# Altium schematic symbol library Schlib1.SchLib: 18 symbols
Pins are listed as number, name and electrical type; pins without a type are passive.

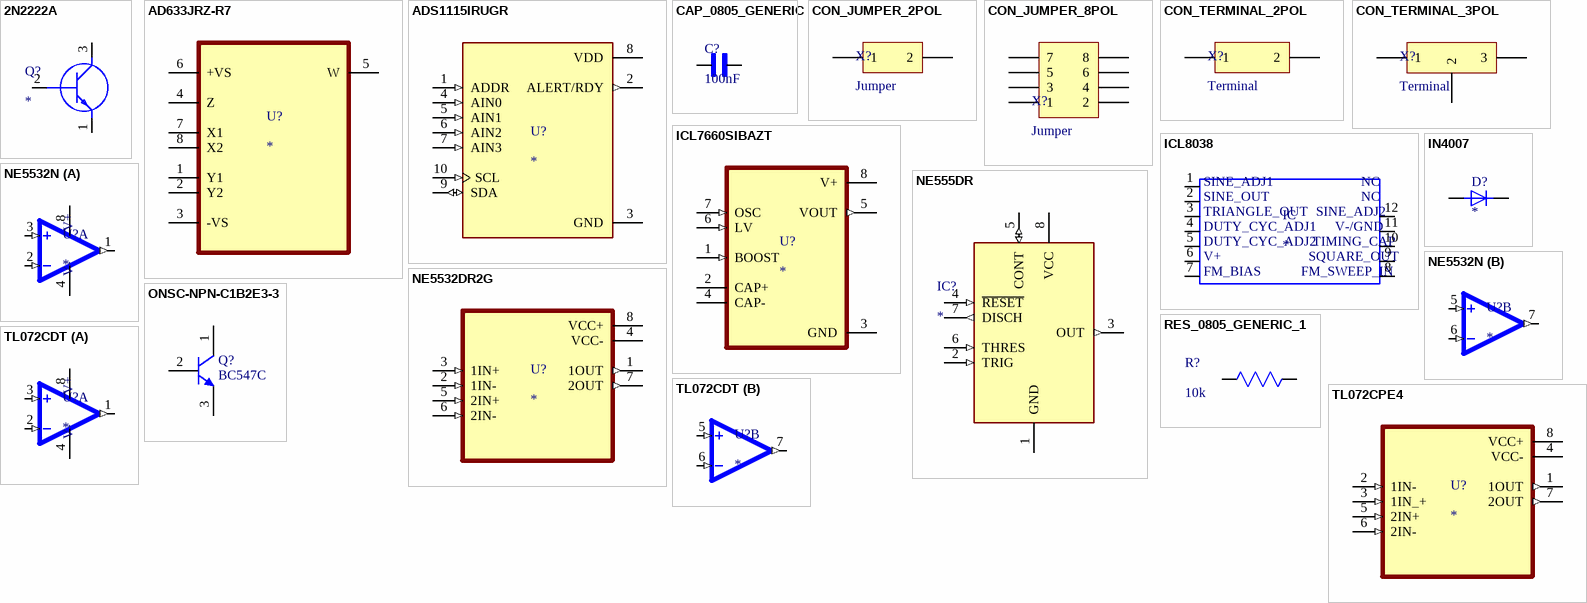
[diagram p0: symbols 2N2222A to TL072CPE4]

## 2N2222A
designator Q?
Transistor BJT NPN; Manufacturer_Name: Diotec; Manufacturer_Part_Number: 2N2222A
footprint 2N2222A
pins: 1 E, 2 B, 3 C

## AD633JRZ-R7
designator U?
Analog Multiplier 4-Quadrant 8-SOIC; MF: Analog Devices; MP: AD633AR
footprint SOIC127P600X175-8N
pins: 1 Y1, 2 Y2, 3 -VS (power), 4 Z, 5 W, 6 +VS (power), 7 X1, 8 X2

## ADS1115IRUGR
designator U?
16-bit, 860-SPS, 4-channel, delta-sigma ADC with PGA, oscillator, VREF, comparator and I2C; MF: Texas Instruments; MP: ADS1115IRUGR
footprint IC_ADS1115IRUGR
pins: 1 ADDR (in), 2 ALERT/RDY (out), 3 GND (power), 4 AIN0 (in), 5 AIN1 (in), 6 AIN2 (in), 7 AIN3 (in), 8 VDD (power), 9 SDA (io), 10 SCL (in)

## CAP_0805_GENERIC
designator C?, comment 100nF
0.1 ÂµF Â±10% 50V Ceramic Capacitor X7R 0805 (2012 Metric); MF: Samsung Electro-Mechanics; MP: CL21B104KBCNNNC
footprint CAPC2012X95N
pins: 1, 2

## CON_JUMPER_2POL
designator X?, comment Jumper
Manufacturer_Name: Yageo; Manufacturer_Part_Number: RC0805FR-0710KL; Value: 10k
footprint CON_JUMPER_2POL (Jumper)
pins: 1, 2

## CON_JUMPER_8POL
designator X?, comment Jumper
Manufacturer_Name: Yageo; Manufacturer_Part_Number: RC0805FR-0710KL; Value: 10k
footprint CON_JUMPER_8POL (Jumper)
pins: 1, 2, 3, 4, 5, 6, 7, 8

## CON_TERMINAL_2POL
designator X?, comment Terminal
Terminal Screw; Manufacturer_Name: Yageo; Manufacturer_Part_Number: RC0805FR-0710KL; Value: 10k
footprint CON_TERMINAL_2POL (Terminal Screw)
pins: 1, 2

## CON_TERMINAL_3POL
designator X?, comment Terminal
Terminal block; Manufacturer_Name: Yageo; Manufacturer_Part_Number: RC0805FR-0710KL; Value: 10k
footprint CON_TERMINAL_3POL (Terminal Screw)
pins: 1, 2, 3

## ICL7660SIBAZT
designator U?
Charge Pump Switching Regulator IC Positive or Negative Fixed -Vin, 2Vin 1 Output 45mA 8-SOIC (0.154, 3.90mm Width); MF: Renesas Electronics America Inc; MP: ICL7660SIBAZT
footprint SOIC127P600X175-8N
pins: 1 BOOST (in), 2 CAP+, 3 GND (power), 4 CAP-, 5 VOUT (out), 6 LV (in), 7 OSC (in), 8 V+ (power)

## ICL8038
designator IC
IC OSCILL GEN/VOLT CONTROL 14DIP; MF: Renesas Electronics; MP: ICL8038
footprint ICL8038
pins: 1, 2, 3, 4, 5, 6, 7, 8, 9, 10, 11, 12

## IN4007
designator D?
Diode Standard 1000 V 1A Through Hole DO-204AL (DO-41); MF: Vishay Semiconductor; MP: IN4007
footprint DIOAD1070W78L470D235P
pins: A, C

## NE555DR
designator IC?
Integrated Circuit; Manufacturer_Name: Texas Instruments; Manufacturer_Part_Number: NE555DR
footprint SOIC127P600X175-8N
pins: 1 GND (power), 2 TRIG (in), 3 OUT (out), 4 ~{RESET} (in), 5 CONT (io), 6 THRES (in), 7 DISCH (out), 8 VCC (power)

## NE5532DR2G
designator U?
NE Series 9 V/us 22 V SMT Dual Low Noise Operational Amplifier - SOIC-16W; MP: NE5532DR2G; MF: ON Semiconductor
footprint SOIC127P599X175-8N
pins: 1 1OUT (out), 2 1IN- (in), 3 1IN+ (in), 4 VCC- (power), 5 2IN+ (in), 6 2IN- (in), 7 2OUT (out), 8 VCC+ (power)

## NE5532N
designator U?
IC, OP AMP, DUAL; No. of Amplifiers: 2 Amplifier; Bandwidth: 10MHz; Slew Rate: 8V/Âµs; Supply Voltage Range: Â± 15V; Amplifier Case Style: DIP; No. of Pins: 8Pins; Operating Temperature Min: 0Â°C; Operating Temperature Max: 70Â°C; MSL: -; SVHC: No SVHC (1; MF: Fairchild Semiconductor; MP: NE5532N
footprint DIP766W45P254L1016H533Q8
part A pins: 1 OUTA (out), 2 -INA (in), 3 +INA (in), 4 V- (power), 8 V+ (power)
part B pins: 5 +INB (in), 6 -INB (in), 7 OUTB (out)

## ONSC-NPN-C1B2E3-3
designator Q?, comment BC547C
Amplifier Transistor, NPN Silicon, 3-Pin TO-92, Bulk Box; Manufacturer: On Semiconductor; IC Continuous (A): 0.1; fT Min (MHz): 150
footprint ONSC-TO-92-3-29-11 (TO, 3-Leads, Body Dia 4.7mm, Pitch 1.27mm)
pins: 1 C, 2 B, 3 E

## RES_0805_GENERIC_1
designator R?, comment 10k
Description; Manufacturer_Name: Yageo; Manufacturer_Part_Number: RC0805FR-0710KL
footprint RC0805N_YAG-M
pins: 1, 2

## TL072CDT
designator U?
Dual Low-Noise JFET-Input General-Purpose Operational Amplifier 8-SOIC 0 to 70; MF: STMicroelectronics; MP: TL072CD
footprint SOIC127P600X175-8N
part A pins: 1 OUT1 (out), 2 -IN1 (in), 3 +IN1 (in), 4 V- (power), 8 V+ (power)
part B pins: 5 +IN2 (in), 6 -IN2 (in), 7 OUT2 (out)

## TL072CPE4
designator U?
Dual Low-Noise JFET-Input General-Purpose Operational Amplifier 8-PDIP 0 to 70; MF: Texas Instruments; MP: TL072CPE4
footprint DIP794W45P254L959H508Q8
pins: 1 1OUT (out), 2 1IN- (in), 3 1IN_+ (in), 4 VCC- (power), 5 2IN+ (in), 6 2IN- (in), 7 2OUT (out), 8 VCC+ (power)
